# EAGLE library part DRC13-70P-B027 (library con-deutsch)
DRC13-70P-B027 Source: DRC13_70P_B027_051010_Einbau_00.pdf
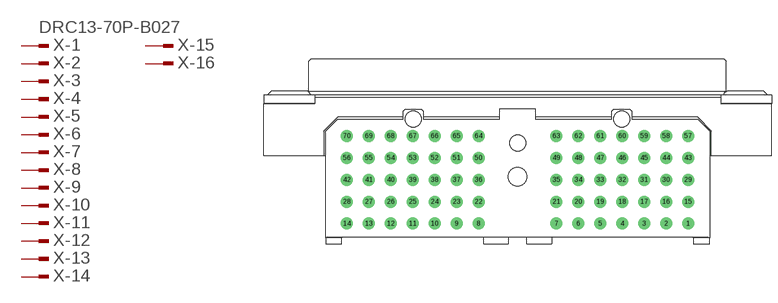
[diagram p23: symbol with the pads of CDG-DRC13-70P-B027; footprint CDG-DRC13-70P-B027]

Designator prefix X; gates -1=PINM_VAL -2=PINM -3=PINM -4=PINM -5=PINM -6=PINM -7=PINM -8=PINM -9=PINM -10=PINM -11=PINM -12=PINM -13=PINM -14=PINM -15=PINM -16=PINM -17=PINM -18=PINM -19=PINM -20=PINM -21=PINM -22=PINM -23=PINM -24=PINM -25=PINM -26=PINM -27=PINM -28=PINM -29=PINM -30=PINM -31=PINM -32=PINM -33=PINM -34=PINM -35=PINM -36=PINM -37=PINM -38=PINM -39=PINM -40=PINM -41=PINM -42=PINM -43=PINM -44=PINM -45=PINM -46=PINM -47=PINM -48=PINM -49=PINM -50=PINM -51=PINM -52=PINM -53=PINM -54=PINM -55=PINM -56=PINM -57=PINM -58=PINM -59=PINM -60=PINM -61=PINM -62=PINM -63=PINM -64=PINM -65=PINM -66=PINM -67=PINM -68=PINM -69=PINM -70=PINM

## DRC13-70P-B027 (OC_FARNELL: unknown; OC_NEWARK: unknown)  [CDG-DRC13-70P-B027]
1  -1:1  pas
2  -2:1  pas
3  -3:1  pas
4  -4:1  pas
5  -5:1  pas
6  -6:1  pas
7  -7:1  pas
8  -8:1  pas
9  -9:1  pas
10  -10:1  pas
11  -11:1  pas
12  -12:1  pas
13  -13:1  pas
14  -14:1  pas
15  -15:1  pas
16  -16:1  pas
17  -17:1  pas
18  -18:1  pas
19  -19:1  pas
20  -20:1  pas
21  -21:1  pas
22  -22:1  pas
23  -23:1  pas
24  -24:1  pas
25  -25:1  pas
26  -26:1  pas
27  -27:1  pas
28  -28:1  pas
29  -29:1  pas
30  -30:1  pas
31  -31:1  pas
32  -32:1  pas
33  -33:1  pas
34  -34:1  pas
35  -35:1  pas
36  -36:1  pas
37  -37:1  pas
38  -38:1  pas
39  -39:1  pas
40  -40:1  pas
41  -41:1  pas
42  -42:1  pas
43  -43:1  pas
44  -44:1  pas
45  -45:1  pas
46  -46:1  pas
47  -47:1  pas
48  -48:1  pas
49  -49:1  pas
50  -50:1  pas
51  -51:1  pas
52  -52:1  pas
53  -53:1  pas
54  -54:1  pas
55  -55:1  pas
56  -56:1  pas
57  -57:1  pas
58  -58:1  pas
59  -59:1  pas
60  -60:1  pas
61  -61:1  pas
62  -62:1  pas
63  -63:1  pas
64  -64:1  pas
65  -65:1  pas
66  -66:1  pas
67  -67:1  pas
68  -68:1  pas
69  -69:1  pas
70  -70:1  pas

## Footprint CDG-DRC13-70P-B027 (pad centres in mm)
DRC13-70P-B027 Source: DRC13_70P_B027_051010_Einbau_00.pdf
drill 2 pad 3 round: 1 42.649,-11.747; 2 37.162,-11.747; 3 31.676,-11.747; 4 26.189,-11.747; 5 20.702,-11.747; 6 15.216,-11.747; 7 9.729,-11.747; 8 -9.729,-11.747; 9 -15.216,-11.747; 10 -20.702,-11.747; 11 -26.189,-11.747; 12 -31.676,-11.747; 13 -37.162,-11.747; 14 -42.649,-11.747; 15 42.649,-6.26; 16 37.162,-6.26; 17 31.676,-6.26; 18 26.189,-6.26; 19 20.702,-6.26; 20 15.216,-6.26; 21 9.729,-6.26; 22 -9.729,-6.26; 23 -15.216,-6.26; 24 -20.702,-6.26; 25 -26.189,-6.26; 26 -31.676,-6.26; 27 -37.162,-6.26; 28 -42.649,-6.26; 29 42.649,-0.773; 30 37.162,-0.773; 31 31.676,-0.773; 32 26.189,-0.773; 33 20.702,-0.773; 34 15.216,-0.773; 35 9.729,-0.773; 36 -9.729,-0.773; 37 -15.216,-0.773; 38 -20.702,-0.773; 39 -26.189,-0.773; 40 -31.676,-0.773; 41 -37.162,-0.773; 42 -42.649,-0.773; 43 42.649,4.713; 44 37.162,4.713; 45 31.676,4.713; 46 26.189,4.713; 47 20.702,4.713; 48 15.216,4.713; 49 9.729,4.713; 50 -9.729,4.713; 51 -15.216,4.713; 52 -20.702,4.713; 53 -26.189,4.713; 54 -31.676,4.713; 55 -37.162,4.713; 56 -42.649,4.713; 57 42.649,10.2; 58 37.162,10.2; 59 31.676,10.2; 60 26.189,10.2; 61 20.702,10.2; 62 15.216,10.2; 63 9.729,10.2; 64 -9.729,10.2; 65 -15.216,10.2; 66 -20.702,10.2; 67 -26.189,10.2; 68 -31.676,10.2; 69 -37.162,10.2; 70 -42.649,10.2
hole 4 at 0,8.5
hole 4 at 26.1,14.5
hole 4 at -26.1,14.5
hole 4.6 at 0,0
